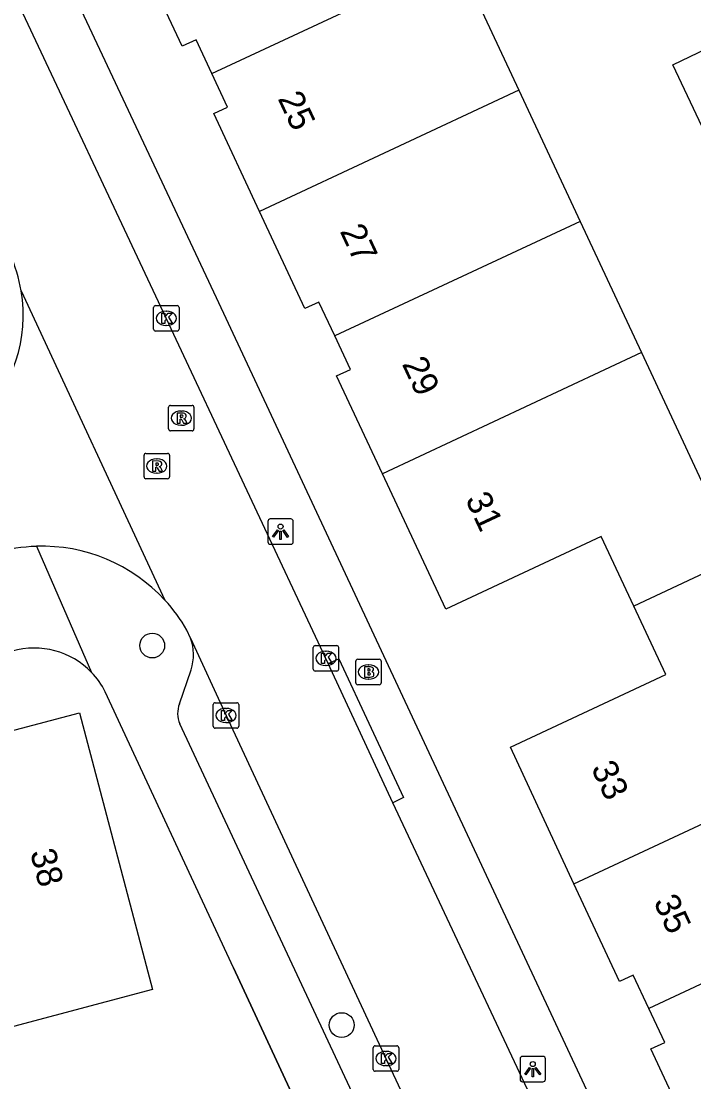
# Model space of a CAD drawing. Extents: x 162880 to 165536, y 384011 to 385179.
# Drawn here: x 163872.2 to 163898.66, y 384364.8 to 384406.52 of the extents above; entities that cross this region are included whole.
import ezdxf

# ---------------------------------------------------------------- set-up
doc = ezdxf.new("R2010")
doc.units = 0
for name, color, linetype in [('IMGEO_Boom', 7, 'Continuous'), ('IMGEO_Brandkraan', 7, 'Continuous'), ('IMGEO_Kolk', 7, 'Continuous'), ('IMGEO_Lichtpunt', 7, 'Continuous'), ('IMGEO_Muur', 7, 'Continuous'), ('IMGEO_Pand', 7, 'Continuous'), ('IMGEO_Pand_nummerreeks', 7, 'Continuous'), ('IMGEO_Rijbaan_lokaal_gesloten', 7, 'Continuous'), ('IMGEO_Rijbaan_lokaal_open', 7, 'Continuous'), ('IMGEO_Rioolput', 7, 'Continuous'), ('IMGEO_Voetpad_open', 7, 'Continuous')]:
    doc.layers.add(name, color=color, linetype=linetype)

msp = doc.modelspace()

# ---------------------------------------------------------------- linework, layer by layer
at = {"layer": 'IMGEO_Boom'}
for centre in [(163877.352, 384381.96), (163884.809, 384367.03)]:
    msp.add_circle(centre, 0.489, dxfattribs=at)
at = {"layer": 'IMGEO_Brandkraan'}
for p, q in [((163885.362, 384380.492), (163885.362, 384381.344)), ((163885.437, 384381.418), (163886.289, 384381.418)), ((163885.85, 384381.198), (163885.875, 384381.198)), ((163886.363, 384381.344), (163886.363, 384380.492)), ((163885.873, 384380.638), (163885.848, 384380.638)), ((163886.289, 384380.418), (163885.437, 384380.418))]:
    msp.add_line(p, q, dxfattribs=at)
for points in [[(163885.362, 384380.492), (163885.362, 384381.344)], [(163885.437, 384381.418), (163886.289, 384381.418)], [(163885.71, 384381.118), (163885.71, 384380.718), (163885.923, 384380.718)], [(163885.941, 384381.118), (163885.71, 384381.118)], [(163885.889, 384381.037), (163885.835, 384381.037), (163885.835, 384380.961)], [(163886.363, 384381.344), (163886.363, 384380.492)], [(163885.835, 384380.961), (163885.888, 384380.961)], [(163885.897, 384380.885), (163885.835, 384380.885), (163885.835, 384380.804)], [(163885.835, 384380.804), (163885.897, 384380.804)], [(163886.289, 384380.418), (163885.437, 384380.418)]]:
    msp.add_lwpolyline(points, dxfattribs=at)
for centre, radius, start, end in [((163885.439, 384381.342), 0.0765, 91.552, 178.448), ((163885.439, 384381.342), 0.0765, 91.552, 178.448), ((163885.89, 384380.999), 0.0379, 267.8285, 90.9355), ((163885.945, 384380.973), 0.145, 59.4692, 91.5367), ((163885.97, 384381.02), 0.0922, 285.5137, 58.1501), ((163886.287, 384381.342), 0.0765, 1.552, 88.448), ((163886.287, 384381.342), 0.0765, 1.552, 88.448), ((163885.898, 384380.844), 0.0404, 269.8759, 90.5077), ((163885.929, 384380.969), 0.251, 268.6676, 293.5347), ((163885.975, 384380.828), 0.105, 301.3115, 78.989), ((163885.439, 384380.494), 0.0765, 181.552, 268.448), ((163885.439, 384380.494), 0.0765, 181.552, 268.448), ((163886.287, 384380.494), 0.0765, 271.552, 358.448), ((163886.287, 384380.494), 0.0765, 271.552, 358.448)]:
    msp.add_arc(centre, radius, start, end, dxfattribs=at)
for centre, major_axis, ratio, start_param, end_param in [((163885.849, 384380.918), (-0.387, 0.002), 0.722429, 4.712389, 7.853982), ((163885.874, 384380.918), (-0.39, 0.002), 0.717154, 1.570796, 4.712389)]:
    msp.add_ellipse(centre, major_axis=major_axis, ratio=ratio, start_param=start_param, end_param=end_param, dxfattribs=at)
at = {"layer": 'IMGEO_Kolk'}
for p, q in [((163877.407, 384394.405), (163877.407, 384395.257)), ((163877.482, 384395.331), (163878.334, 384395.331)), ((163878.408, 384395.257), (163878.408, 384394.405)), ((163877.895, 384395.111), (163877.92, 384395.111)), ((163877.918, 384394.551), (163877.893, 384394.551)), ((163878.334, 384394.331), (163877.482, 384394.331)), ((163883.688, 384381.03), (163883.688, 384381.882)), ((163883.763, 384381.956), (163884.615, 384381.956)), ((163884.689, 384381.882), (163884.689, 384381.03)), ((163884.176, 384381.736), (163884.201, 384381.736)), ((163884.199, 384381.176), (163884.174, 384381.176)), ((163884.615, 384380.956), (163883.763, 384380.956)), ((163879.756, 384378.783), (163879.756, 384379.635)), ((163879.831, 384379.709), (163880.683, 384379.709)), ((163880.244, 384379.489), (163880.269, 384379.489)), ((163880.757, 384379.635), (163880.757, 384378.783)), ((163880.267, 384378.929), (163880.242, 384378.929)), ((163880.683, 384378.709), (163879.831, 384378.709)), ((163886.05, 384365.29), (163886.05, 384366.142)), ((163886.125, 384366.216), (163886.977, 384366.216)), ((163886.538, 384365.996), (163886.563, 384365.996)), ((163887.051, 384366.142), (163887.051, 384365.29)), ((163886.977, 384365.216), (163886.125, 384365.216)), ((163886.561, 384365.436), (163886.536, 384365.436))]:
    msp.add_line(p, q, dxfattribs=at)
for points in [[(163877.407, 384394.405), (163877.407, 384395.257)], [(163877.482, 384395.331), (163878.334, 384395.331)], [(163878.408, 384395.257), (163878.408, 384394.405)], [(163877.728, 384395.031), (163877.851, 384395.031), (163877.851, 384394.88), (163877.981, 384395.031), (163878.145, 384395.031), (163877.999, 384394.88), (163878.152, 384394.631), (163878, 384394.631), (163877.915, 384394.795), (163877.851, 384394.728), (163877.851, 384394.631), (163877.728, 384394.631), (163877.728, 384395.031)], [(163878.334, 384394.331), (163877.482, 384394.331)], [(163883.688, 384381.03), (163883.688, 384381.882)], [(163883.763, 384381.956), (163884.615, 384381.956)], [(163884.689, 384381.882), (163884.689, 384381.03)], [(163884.009, 384381.656), (163884.132, 384381.656), (163884.132, 384381.505), (163884.262, 384381.656), (163884.426, 384381.656), (163884.28, 384381.505), (163884.433, 384381.256), (163884.281, 384381.256), (163884.196, 384381.42), (163884.132, 384381.353), (163884.132, 384381.256), (163884.009, 384381.256), (163884.009, 384381.656)], [(163884.615, 384380.956), (163883.763, 384380.956)], [(163879.756, 384378.783), (163879.756, 384379.635)], [(163879.831, 384379.709), (163880.683, 384379.709)], [(163880.077, 384379.409), (163880.2, 384379.409), (163880.2, 384379.258), (163880.33, 384379.409), (163880.494, 384379.409), (163880.348, 384379.258), (163880.501, 384379.009), (163880.349, 384379.009), (163880.264, 384379.173), (163880.2, 384379.106), (163880.2, 384379.009), (163880.077, 384379.009), (163880.077, 384379.409)], [(163880.757, 384379.635), (163880.757, 384378.783)], [(163880.683, 384378.709), (163879.831, 384378.709)], [(163886.05, 384365.29), (163886.05, 384366.142)], [(163886.125, 384366.216), (163886.977, 384366.216)], [(163887.051, 384366.142), (163887.051, 384365.29)], [(163886.371, 384365.916), (163886.494, 384365.916), (163886.494, 384365.765), (163886.624, 384365.916), (163886.788, 384365.916), (163886.642, 384365.765), (163886.795, 384365.516), (163886.643, 384365.516), (163886.558, 384365.68), (163886.494, 384365.613), (163886.494, 384365.516), (163886.371, 384365.516), (163886.371, 384365.916)], [(163886.977, 384365.216), (163886.125, 384365.216)]]:
    msp.add_lwpolyline(points, dxfattribs=at)
for centre, start, end in [((163877.484, 384395.255), 91.552, 178.448), ((163877.484, 384395.255), 91.552, 178.448), ((163878.332, 384395.255), 1.552, 88.448), ((163878.332, 384395.255), 1.552, 88.448), ((163877.484, 384394.407), 181.552, 268.448), ((163877.484, 384394.407), 181.552, 268.448), ((163878.332, 384394.407), 271.552, 358.448), ((163878.332, 384394.407), 271.552, 358.448), ((163883.765, 384381.88), 91.552, 178.448), ((163883.765, 384381.88), 91.552, 178.448), ((163884.613, 384381.88), 1.552, 88.448), ((163884.613, 384381.88), 1.552, 88.448), ((163883.765, 384381.032), 181.552, 268.448), ((163883.765, 384381.032), 181.552, 268.448), ((163884.613, 384381.032), 271.552, 358.448), ((163884.613, 384381.032), 271.552, 358.448), ((163879.833, 384379.633), 91.552, 178.448), ((163879.833, 384379.633), 91.552, 178.448), ((163880.681, 384379.633), 1.552, 88.448), ((163880.681, 384379.633), 1.552, 88.448), ((163879.833, 384378.785), 181.552, 268.448), ((163879.833, 384378.785), 181.552, 268.448), ((163880.681, 384378.785), 271.552, 358.448), ((163880.681, 384378.785), 271.552, 358.448), ((163886.127, 384366.14), 91.552, 178.448), ((163886.127, 384366.14), 91.552, 178.448), ((163886.975, 384366.14), 1.552, 88.448), ((163886.975, 384366.14), 1.552, 88.448), ((163886.127, 384365.292), 181.552, 268.448), ((163886.127, 384365.292), 181.552, 268.448), ((163886.975, 384365.292), 271.552, 358.448), ((163886.975, 384365.292), 271.552, 358.448)]:
    msp.add_arc(centre, 0.0765, start, end, dxfattribs=at)
for centre, major_axis, ratio, start_param, end_param in [((163877.894, 384394.831), (-0.387, 0.002), 0.722429, 4.712389, 7.853982), ((163877.919, 384394.831), (-0.39, 0.002), 0.717154, 1.570796, 4.712389), ((163884.175, 384381.456), (-0.387, 0.002), 0.722429, 4.712389, 7.853982), ((163884.2, 384381.456), (-0.39, 0.002), 0.717154, 1.570796, 4.712389), ((163880.243, 384379.209), (-0.387, 0.002), 0.722429, 4.712389, 7.853982), ((163880.268, 384379.209), (-0.39, 0.002), 0.717154, 1.570796, 4.712389), ((163886.537, 384365.716), (-0.387, 0.002), 0.722429, 4.712389, 7.853982), ((163886.562, 384365.716), (-0.39, 0.002), 0.717154, 1.570796, 4.712389)]:
    msp.add_ellipse(centre, major_axis=major_axis, ratio=ratio, start_param=start_param, end_param=end_param, dxfattribs=at)
at = {"layer": 'IMGEO_Lichtpunt'}
for p, q in [((163882.806, 384386.937), (163881.998, 384386.937)), ((163882.806, 384386.937), (163881.998, 384386.937)), ((163881.904, 384386.842), (163881.904, 384386.035)), ((163881.904, 384386.842), (163881.904, 384386.035)), ((163882.9, 384386.035), (163882.9, 384386.842)), ((163882.9, 384386.035), (163882.9, 384386.842)), ((163881.998, 384385.941), (163882.806, 384385.941)), ((163881.998, 384385.941), (163882.806, 384385.941)), ((163891.827, 384365.702), (163891.827, 384364.895)), ((163891.827, 384365.702), (163891.827, 384364.895)), ((163892.729, 384365.797), (163891.921, 384365.797)), ((163892.729, 384365.797), (163891.921, 384365.797)), ((163892.823, 384364.895), (163892.823, 384365.702)), ((163892.823, 384364.895), (163892.823, 384365.702)), ((163891.921, 384364.801), (163892.729, 384364.801)), ((163891.921, 384364.801), (163892.729, 384364.801))]:
    msp.add_line(p, q, dxfattribs=at)
for points in [[(163882.278, 384386.506), (163882.317, 384386.478), (163882.129, 384386.216), (163882.091, 384386.243), (163882.278, 384386.506)], [(163882.38, 384386.458), (163882.427, 384386.458), (163882.427, 384386.136), (163882.38, 384386.136), (163882.38, 384386.458)], [(163882.49, 384386.478), (163882.528, 384386.505), (163882.715, 384386.243), (163882.676, 384386.215), (163882.49, 384386.478)], [(163892.201, 384365.366), (163892.24, 384365.338), (163892.052, 384365.076), (163892.014, 384365.103), (163892.201, 384365.366)], [(163892.303, 384365.318), (163892.35, 384365.318), (163892.35, 384364.996), (163892.303, 384364.996), (163892.303, 384365.318)], [(163892.413, 384365.338), (163892.451, 384365.365), (163892.638, 384365.103), (163892.599, 384365.075), (163892.413, 384365.338)]]:
    msp.add_lwpolyline(points, dxfattribs=at)
for centre in [(163882.403, 384386.64), (163892.326, 384365.5)]:
    msp.add_circle(centre, 0.0994, dxfattribs=at)
for centre, start, end in [((163881.998, 384386.842), 90, 180), ((163881.998, 384386.842), 90, 180), ((163882.806, 384386.842), 0, 90), ((163882.806, 384386.842), 0, 90), ((163881.998, 384386.035), 180, 270), ((163881.998, 384386.035), 180, 270), ((163882.806, 384386.035), 270, 0), ((163882.806, 384386.035), 270, 360), ((163891.921, 384365.702), 90, 180), ((163891.921, 384365.702), 90, 180), ((163892.729, 384365.702), 0, 90), ((163892.729, 384365.702), 0, 90), ((163891.921, 384364.895), 180, 270), ((163891.921, 384364.895), 180, 270), ((163892.729, 384364.895), 270, 0), ((163892.729, 384364.895), 270, 360)]:
    msp.add_arc(centre, 0.0946, start, end, dxfattribs=at)
at = {"layer": 'IMGEO_Muur'}
msp.add_lwpolyline([(163880.548, 384369.283), (163883.096, 384363.799)], dxfattribs=at)
at = {"layer": 'IMGEO_Pand'}
for points in [[(163879.7, 384404.459), (163879.079, 384405.785), (163878.535, 384405.53), (163876.739, 384409.368)], [(163879.7, 384404.459), (163889.359, 384408.969)], [(163889.359, 384408.969), (163891.772, 384403.809)], [(163899.575, 384401.148), (163897.833, 384404.806), (163900.162, 384405.915), (163901.913, 384402.238)], [(163881.578, 384399.033), (163879.774, 384402.887), (163880.317, 384403.141), (163879.7, 384404.459)], [(163891.772, 384403.809), (163881.578, 384399.033)], [(163891.772, 384403.809), (163894.19, 384398.637)], [(163884.534, 384394.135), (163883.908, 384395.471), (163883.364, 384395.216), (163881.578, 384399.033)], [(163894.19, 384398.637), (163884.534, 384394.135)], [(163894.19, 384398.637), (163896.599, 384393.485)], [(163886.412, 384388.708), (163884.607, 384392.564), (163885.15, 384392.818), (163884.534, 384394.135)], [(163896.599, 384393.485), (163886.412, 384388.708)], [(163896.599, 384393.485), (163898.962, 384388.431), (163901.072, 384389.417), (163902.481, 384386.403)], [(163896.299, 384383.507), (163895.015, 384386.25), (163888.901, 384383.389), (163886.412, 384388.708)], [(163902.481, 384386.403), (163896.299, 384383.507)], [(163893.947, 384372.585), (163891.445, 384377.956), (163897.558, 384380.816), (163896.299, 384383.507)], [(163868.771, 384377.805), (163874.486, 384379.311), (163877.359, 384368.434), (163871.695, 384366.927)], [(163893.947, 384372.585), (163904.144, 384377.348)], [(163896.893, 384367.685), (163896.28, 384368.995), (163895.737, 384368.741), (163893.947, 384372.585)], [(163906.554, 384372.196), (163896.893, 384367.685)], [(163898.775, 384362.244), (163896.973, 384366.095), (163897.517, 384366.35), (163896.893, 384367.685)]]:
    msp.add_lwpolyline(points, dxfattribs=at)
at = {"layer": 'IMGEO_Rijbaan_lokaal_gesloten'}
for points in [[(163884.282, 384381.254), (163877.907, 384394.83), (163871.746, 384407.935), (163869.593, 384412.537)], [(163872.197, 384395.912), (163877.851, 384383.748)], [(163878.863, 384382.25), (163878.721, 384382.559)], [(163878.863, 384382.25), (163880.258, 384379.21), (163886.551, 384365.716), (163896.81, 384343.804), (163897.929, 384341.424)], [(163886.822, 384375.777), (163884.282, 384381.254)], [(163896.753, 384354.528), (163894.159, 384360.171), (163886.822, 384375.777)]]:
    msp.add_lwpolyline(points, dxfattribs=at)
for centre, radius, start, end in [((163866.524, 384394.95), 5.754, 9.6229, 24.6162), ((163872.975, 384379.267), 6.622, 29.8065, 42.5799)]:
    msp.add_arc(centre, radius, start, end, dxfattribs=at)
at = {"layer": 'IMGEO_Rijbaan_lokaal_open'}
for centre, radius, start, end in [((163866.542, 384394.954), 5.735, 313.83, 9.6108), ((163873.017, 384379.327), 6.538, 91.9327, 106.2033), ((163873.019, 384379.295), 6.571, 42.6635, 91.9471)]:
    msp.add_arc(centre, radius, start, end, dxfattribs=at)
at = {"layer": 'IMGEO_Rioolput'}
for p, q in [((163877.995, 384390.478), (163877.995, 384391.33)), ((163878.07, 384391.404), (163878.922, 384391.404)), ((163878.483, 384391.184), (163878.508, 384391.184)), ((163878.996, 384391.33), (163878.996, 384390.478)), ((163878.506, 384390.624), (163878.481, 384390.624)), ((163878.922, 384390.404), (163878.07, 384390.404)), ((163877.031, 384388.592), (163877.031, 384389.444)), ((163877.106, 384389.518), (163877.958, 384389.518)), ((163878.032, 384389.444), (163878.032, 384388.592)), ((163877.519, 384389.298), (163877.544, 384389.298)), ((163877.958, 384388.518), (163877.106, 384388.518)), ((163877.542, 384388.738), (163877.517, 384388.738))]:
    msp.add_line(p, q, dxfattribs=at)
for points in [[(163877.995, 384390.478), (163877.995, 384391.33)], [(163878.07, 384391.404), (163878.922, 384391.404)], [(163878.584, 384391.102), (163878.332, 384391.104), (163878.332, 384390.704)], [(163878.51, 384391.023), (163878.456, 384391.023), (163878.456, 384390.942)], [(163878.996, 384391.33), (163878.996, 384390.478)], [(163878.332, 384390.704), (163878.456, 384390.704), (163878.456, 384390.866), (163878.467, 384390.866)], [(163878.456, 384390.942), (163878.508, 384390.942)], [(163878.514, 384390.837), (163878.585, 384390.704), (163878.725, 384390.704), (163878.66, 384390.83)], [(163878.922, 384390.404), (163878.07, 384390.404)], [(163877.031, 384388.592), (163877.031, 384389.444)], [(163877.106, 384389.518), (163877.958, 384389.518)], [(163878.032, 384389.444), (163878.032, 384388.592)], [(163877.62, 384389.216), (163877.368, 384389.218), (163877.368, 384388.818)], [(163877.368, 384388.818), (163877.492, 384388.818), (163877.492, 384388.98), (163877.503, 384388.98)], [(163877.546, 384389.137), (163877.492, 384389.137), (163877.492, 384389.056)], [(163877.492, 384389.056), (163877.544, 384389.056)], [(163877.55, 384388.951), (163877.621, 384388.818), (163877.761, 384388.818), (163877.696, 384388.944)], [(163877.958, 384388.518), (163877.106, 384388.518)]]:
    msp.add_lwpolyline(points, dxfattribs=at)
for centre, radius, start, end in [((163878.072, 384391.328), 0.0765, 91.552, 178.448), ((163878.072, 384391.328), 0.0765, 91.552, 178.448), ((163878.516, 384390.927), 0.0964, 77.0061, 93.1865), ((163878.53, 384390.984), 0.0378, 276.6634, 79.6772), ((163878.583, 384390.992), 0.109, 350.3612, 89.416), ((163878.92, 384391.328), 0.0765, 1.552, 88.448), ((163878.92, 384391.328), 0.0765, 1.552, 88.448), ((163878.466, 384390.813), 0.0533, 26.0293, 88.6989), ((163878.492, 384391.131), 0.19, 274.7715, 282.9687), ((163878.581, 384390.992), 0.112, 277.5842, 350.9817), ((163878.565, 384390.777), 0.108, 29.5134, 73.7905), ((163878.072, 384390.48), 0.0765, 181.552, 268.448), ((163878.072, 384390.48), 0.0765, 181.552, 268.448), ((163878.92, 384390.48), 0.0765, 271.552, 358.448), ((163878.92, 384390.48), 0.0765, 271.552, 358.448), ((163877.108, 384389.442), 0.0765, 91.552, 178.448), ((163877.108, 384389.442), 0.0765, 91.552, 178.448), ((163877.956, 384389.442), 0.0765, 1.552, 88.448), ((163877.956, 384389.442), 0.0765, 1.552, 88.448), ((163877.502, 384388.927), 0.0533, 26.0293, 88.6989), ((163877.528, 384389.245), 0.19, 274.7715, 282.9687), ((163877.552, 384389.041), 0.0964, 77.0061, 93.1865), ((163877.566, 384389.098), 0.0378, 276.6634, 79.6772), ((163877.619, 384389.106), 0.109, 350.3612, 89.416), ((163877.617, 384389.106), 0.112, 277.5842, 350.9817), ((163877.601, 384388.891), 0.108, 29.5134, 73.7905), ((163877.108, 384388.594), 0.0765, 181.552, 268.448), ((163877.108, 384388.594), 0.0765, 181.552, 268.448), ((163877.956, 384388.594), 0.0765, 271.552, 358.448), ((163877.956, 384388.594), 0.0765, 271.552, 358.448)]:
    msp.add_arc(centre, radius, start, end, dxfattribs=at)
for centre, major_axis, ratio, start_param, end_param in [((163878.482, 384390.904), (-0.387, 0.002), 0.722429, 4.712389, 7.853982), ((163878.507, 384390.904), (-0.39, 0.002), 0.717154, 1.570796, 4.712389), ((163877.518, 384389.018), (-0.387, 0.002), 0.722429, 4.712389, 7.853982), ((163877.543, 384389.018), (-0.39, 0.002), 0.717154, 1.570796, 4.712389)]:
    msp.add_ellipse(centre, major_axis=major_axis, ratio=ratio, start_param=start_param, end_param=end_param, dxfattribs=at)
at = {"layer": 'IMGEO_Voetpad_open'}
for points in [[(163855.833, 384446.756), (163856.489, 384445.365), (163879.872, 384395.646), (163899.152, 384354.419), (163903.1, 384352.953), (163905.674, 384354.206), (163909.593, 384345.84)], [(163872.796, 384385.862), (163874.967, 384380.901)], [(163884.282, 384381.254), (163884.691, 384381.436), (163887.24, 384375.985), (163886.822, 384375.777)], [(163878.427, 384379.671), (163878.882, 384381.006)], [(163883.096, 384363.799), (163880.548, 384369.283), (163875.505, 384380.136)], [(163885.219, 384364.381), (163878.436, 384378.881)]]:
    msp.add_lwpolyline(points, dxfattribs=at)
for centre, radius, start, end in [((163872.722, 384378.751), 3.109, 43.7677, 106.3877), ((163877.037, 384381.6), 1.939, 342.1584, 19.5917), ((163872.732, 384378.758), 3.096, 26.4313, 43.8036), ((163879.348, 384379.286), 0.998, 157.3361, 203.9693)]:
    msp.add_arc(centre, radius, start, end, dxfattribs=at)

# ---------------------------------------------------------------- texts
at = {"layer": 'IMGEO_Pand_nummerreeks'}
for s, rotation, p in [('25', 295.0854, (163882.278, 384403.478)), ('27', 295.0854, (163884.722, 384398.258)), ('29', 295.0854, (163887.166, 384393.037)), ('31', 295.0854, (163889.658, 384387.714)), ('33', 295.0252, (163894.607, 384377.141)), ('38', 284.7959, (163872.541, 384373.831)), ('35', 295.0252, (163897.063, 384371.882))]:
    msp.add_text(s, height=1, rotation=rotation, dxfattribs=at).set_placement(p)

doc.saveas('drawing.dxf')
